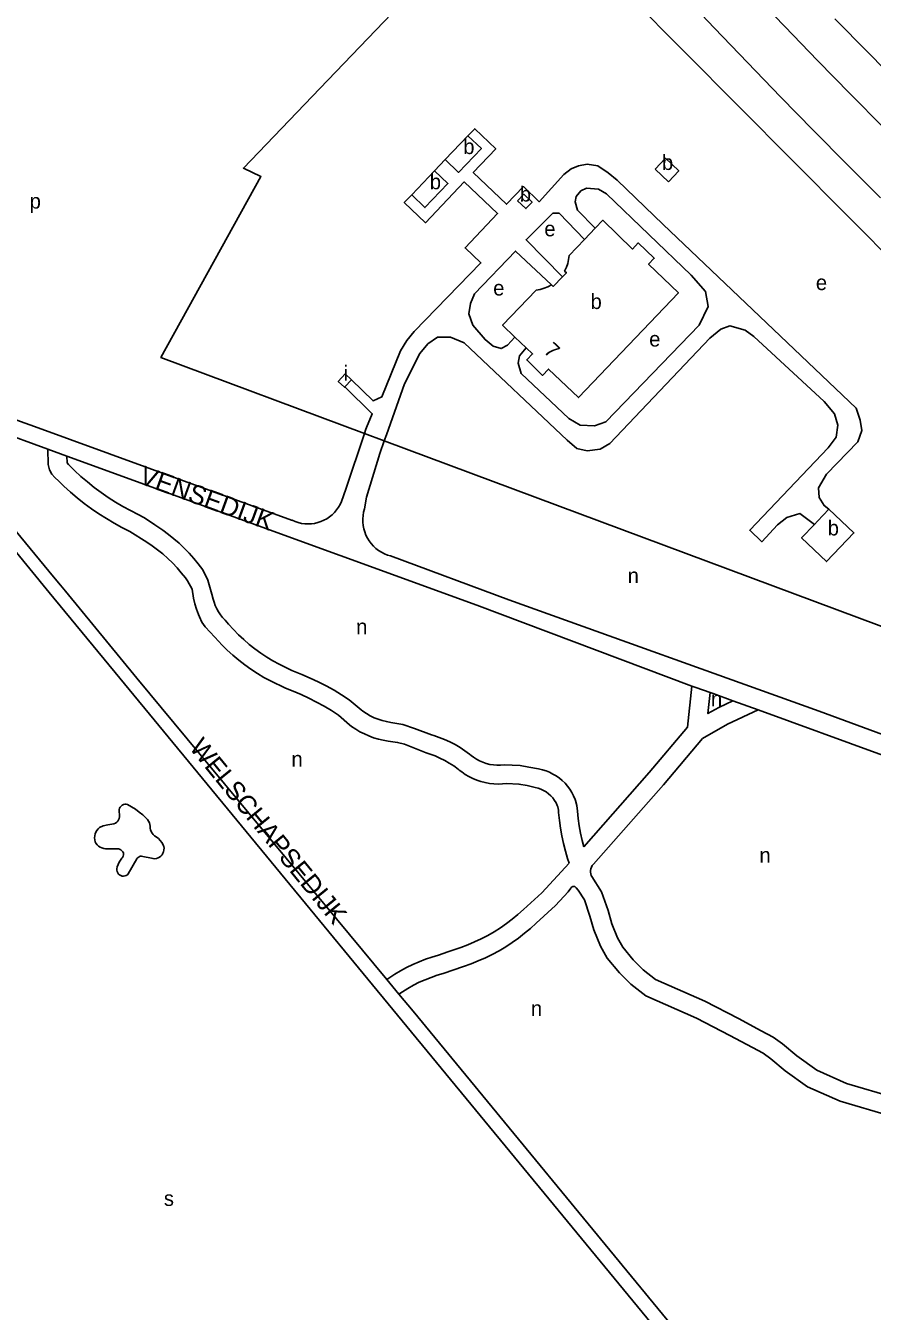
# Model space of a CAD drawing. Extents: x 156066 to 157805, y 383432 to 385631.
# Drawn here: x 156622.4 to 156846.9, y 384832 to 385173.1 of the extents above; entities that cross this region are included whole.
import ezdxf

# ---------------------------------------------------------------- set-up
doc = ezdxf.new("R2010")
doc.units = 0
for name, color, linetype in [('BLT_Basislijn', 7, 'Continuous'), ('BLT_Bebouwing', 7, 'Continuous'), ('BLT_Centroide', 7, 'Continuous'), ('BLT_Huisnummer', 7, 'Continuous'), ('BLT_Straatnaam', 7, 'Continuous')]:
    doc.layers.add(name, color=color, linetype=linetype)

msp = doc.modelspace()

# ---------------------------------------------------------------- linework, layer by layer
at = {"layer": 'BLT_Basislijn'}
for p, q in [((156700.39, 385156.45), (156745.33, 385203.34)), ((156895.07, 385067.48), (156766.62, 385196.86)), ((156733.63, 385137.58), (156730.82, 385134.59)), ((156603.38, 385069.8), (156628.27, 385060.73)), ((156624.71, 385066.73), (156617.54, 385069.34)), ((156692.93, 385041.93), (156624.71, 385066.73)), ((156717.48, 385062.97), (156712.23, 385064.93)), ((156718.04, 385064.52), (156717.48, 385062.97)), ((156871.24, 385005.53), (156717.48, 385062.97)), ((156628.27, 385060.73), (156628.39, 385056.66)), ((156628.27, 385060.73), (156633.33, 385058.89)), ((156633.33, 385058.89), (156633.38, 385057.07)), ((156633.33, 385058.89), (156741.99, 385019.31)), ((156609.93, 385045.44), (156628.64, 385022.72)), ((156619.86, 385038.85), (156629.74, 385026.88)), ((156650.05, 385038.91), (156654.52, 385036.03)), ((156719.12, 385032.41), (156750.56, 385020.74)), ((156629.74, 385026.88), (156631.6, 385024.62)), ((156631.6, 385024.62), (156632.92, 385023.02)), ((156628.64, 385022.72), (156647.34, 385000)), ((156632.92, 385023.02), (156651.9, 385000)), ((156750.56, 385020.74), (156832.8, 384991.18)), ((156799.07, 384997.88), (156741.99, 385019.31)), ((156689.64, 385003.65), (156692.96, 385001.98)), ((156647.34, 385000), (156763.61, 384858.81)), ((156651.9, 385000), (156718.17, 384919.98)), ((156687.33, 384999.22), (156691.26, 384997.28)), ((156799.07, 384997.88), (156797.88, 384986.98)), ((156800.13, 384997.48), (156799.07, 384997.88)), ((156803.91, 384996.14), (156800.13, 384997.48)), ((156708.18, 384994.26), (156711.34, 384991.55)), ((156804.66, 384995.87), (156803.91, 384996.14)), ((156804.66, 384995.87), (156809.95, 384993.95)), ((156809.95, 384993.95), (156816.62, 384991.54)), ((156705.39, 384990.11), (156708.26, 384987.6)), ((156861.75, 384980.58), (156832.8, 384991.18)), ((156740.12, 384979.78), (156740.54, 384979.45)), ((156737.04, 384975.84), (156737.38, 384975.57)), ((156647.21, 384964.76), (156647.24, 384963.57)), ((156643.56, 384954.72), (156646.61, 384954.68)), ((156655.73, 384952.18), (156653.43, 384952.66)), ((156651.88, 384952.06), (156649.62, 384948.06)), ((156766.5, 384950.92), (156759.23, 384943.01)), ((156754.38, 384938.6), (156759.23, 384943.01)), ((156766.28, 384943.3), (156762.91, 384939.62)), ((156766.28, 384943.3), (156766.98, 384944.25)), ((156768.39, 384944.35), (156768.93, 384943.69)), ((156757.81, 384934.96), (156762.91, 384939.62)), ((156733.15, 384921.6), (156738.54, 384923.46)), ((156718.17, 384919.98), (156721.37, 384916.12)), ((156721.37, 384916.12), (156725.11, 384911.6)), ((156725.11, 384911.6), (156823.88, 384791.69)), ((156763.61, 384858.81), (156843.95, 384761.22))]:
    msp.add_line(p, q, dxfattribs=at)
for points in [[(156849.91, 385146.05), (156841.11, 385154.93), (156832.37, 385163.86), (156823.68, 385172.84), (156815.04, 385181.87), (156806.47, 385190.96), (156797.94, 385200.1), (156789.48, 385209.29), (156781.07, 385218.54), (156772.72, 385227.84), (156764.42, 385237.18), (156756.19, 385246.58), (156748.01, 385256.03), (156739.89, 385265.53), (156731.83, 385275.08), (156723.83, 385284.68), (156715.89, 385294.33), (156708, 385304.03), (156700.18, 385313.78), (156692.42, 385323.57), (156684.72, 385333.41), (156677.08, 385343.3), (156669.5, 385353.24), (156661.98, 385363.22)], [(156849.1, 385127.46), (156840.18, 385136.34), (156831.32, 385145.28), (156822.52, 385154.26), (156813.77, 385163.31), (156805.07, 385172.4), (156796.44, 385181.55), (156787.86, 385190.76), (156779.34, 385200.01)], [(156854.62, 385156.98), (156845.78, 385165.94), (156836.99, 385174.95)], [(156712.23, 385064.93), (156658.24, 385085.09), (156684.8, 385133.04), (156680.12, 385135.3), (156700.39, 385156.45)], [(156739.69, 385143.89), (156741.46, 385145.75), (156747.06, 385140.41), (156741.09, 385134.15), (156749.93, 385125.72), (156754.39, 385130.4), (156758.6, 385126.39), (156765.14, 385133.58), (156767.06, 385135.08), (156768.98, 385135.93), (156771.33, 385136.36), (156774.1, 385135.93), (156776.88, 385134.01), (156779.23, 385132.09)], [(156724.76, 385128.23), (156722.79, 385126.17), (156728.39, 385120.83), (156738.71, 385131.65), (156747.55, 385123.22), (156738.9, 385114.15), (156743.12, 385110.14), (156725.42, 385091.92), (156723.5, 385089.57), (156721.79, 385086.8), (156716.88, 385074.62), (156714.54, 385073.55), (156708.79, 385079.13)], [(156755.09, 385087.66), (156753.39, 385085.51), (156752.97, 385083.59), (156753.82, 385080.81), (156766.42, 385068.85), (156769.41, 385067.14), (156773.25, 385066.93), (156776.24, 385067.99), (156801.01, 385093.63), (156803.36, 385098.55), (156802.71, 385102.61), (156798.87, 385106.88), (156776.45, 385128.46), (156774.32, 385129.74), (156771.12, 385129.95), (156769.62, 385129.31), (156768.34, 385127.81), (156768.13, 385126.32), (156768.77, 385124.18), (156773.41, 385119.34)], [(156779.23, 385132.09), (156791.4, 385120.34), (156842.64, 385071.63), (156843.71, 385068.42), (156844.14, 385065.65), (156843.07, 385062.65), (156834.74, 385054.11), (156832.61, 385050.48), (156832.82, 385047.91), (156834.1, 385045.78), (156835.39, 385044.78)], [(156770.58, 385116.38), (156763.86, 385123.33), (156762.15, 385123.33), (156755.1, 385116.28), (156764.71, 385106.45)], [(156761.8, 385104.33), (156752.33, 385113.29), (156741.44, 385101.96), (156740.37, 385099.4), (156739.94, 385096.62), (156741.01, 385093.63), (156744.21, 385089.79), (156746.35, 385088.08), (156748.48, 385087.44), (156750.19, 385088.29), (156752.15, 385090.48)], [(156831.56, 385040.74), (156827.7, 385043.64), (156824.28, 385042.57), (156821.72, 385040.65), (156817.62, 385036.15), (156814.39, 385039.23), (156835.21, 385061.1), (156837.3, 385063.94), (156837.73, 385067.14), (156836.88, 385070.13), (156834.1, 385073.34), (156815.52, 385090.64), (156813.18, 385092.35), (156809.12, 385093.42), (156806.77, 385092.56), (156803.78, 385090.21), (156777.31, 385062.23), (156774.74, 385060.73), (156771.33, 385060.3), (156768.55, 385060.95), (156765.99, 385063.08), (156738.66, 385088.93), (156735.03, 385090.43), (156731.62, 385090.43), (156729.05, 385088.72), (156726.92, 385086.15), (156722.86, 385078.04), (156718.04, 385064.52)], [(156707.05, 385077.3), (156714.32, 385070.13), (156712.78, 385066.46)], [(156706.16, 385046.89), (156707.28, 385050.12), (156712.23, 385064.93)], [(156712.23, 385064.93), (156712.61, 385066.07), (156712.78, 385066.46)], [(156717.48, 385062.97), (156716.29, 385059.61), (156712.82, 385047.98), (156712.22, 385044.89)], [(156628.39, 385056.66), (156628.75, 385055.26), (156629.37, 385054.11), (156630.15, 385053.2), (156631.15, 385052.21)], [(156652.21, 385043.42), (156650.17, 385044.44), (156648.17, 385045.54), (156646.2, 385046.7), (156644.28, 385047.93), (156642.4, 385049.23), (156640.57, 385050.6), (156638.79, 385052.03), (156637.06, 385053.52), (156635.38, 385055.06), (156633.76, 385056.67), (156633.38, 385057.07)], [(156650.05, 385038.91), (156647.93, 385039.97), (156645.85, 385041.11), (156643.8, 385042.31), (156641.8, 385043.58), (156639.85, 385044.92), (156637.94, 385046.32), (156636.08, 385047.78), (156634.27, 385049.31), (156632.51, 385050.9), (156631.15, 385052.21)], [(156706.16, 385046.89), (156705.8, 385046.09), (156705.36, 385045.34), (156704.86, 385044.62), (156704.29, 385043.95), (156703.67, 385043.34), (156702.99, 385042.78), (156702.27, 385042.29), (156701.5, 385041.87), (156700.7, 385041.52), (156699.87, 385041.25), (156699.02, 385041.05), (156698.15, 385040.93), (156697.27, 385040.89), (156696.4, 385040.93), (156695.53, 385041.05), (156694.68, 385041.25), (156693.85, 385041.52), (156693.05, 385041.87), (156692.93, 385041.93)], [(156712.22, 385044.89), (156711.99, 385044.03), (156711.85, 385043.15), (156711.78, 385042.26), (156711.79, 385041.37), (156711.89, 385040.49), (156712.06, 385039.61), (156712.31, 385038.76), (156712.64, 385037.93), (156713.04, 385037.14), (156713.51, 385036.38), (156714.04, 385035.67), (156714.64, 385035.01), (156715.29, 385034.41), (156715.99, 385033.87), (156716.74, 385033.39), (156717.54, 385032.98), (156718.36, 385032.65), (156719.12, 385032.41)], [(156652.21, 385043.42), (156653.72, 385042.57), (156655.2, 385041.65), (156656.63, 385040.67), (156657.19, 385040.26)], [(156657.19, 385040.26), (156658.74, 385039.23), (156660.25, 385038.13), (156661.71, 385036.97), (156663.12, 385035.75), (156664.47, 385034.47), (156665.77, 385033.13), (156667.01, 385031.74), (156668.18, 385030.3), (156669.36, 385028.72)], [(156654.52, 385036.03), (156655.98, 385035.06), (156657.39, 385034.02), (156658.75, 385032.92), (156660.07, 385031.76), (156661.33, 385030.54), (156662.53, 385029.27), (156663.67, 385027.94), (156664.75, 385026.56), (156665.28, 385025.83)], [(156669.36, 385028.72), (156670.74, 385025.97), (156671.77, 385022.28)], [(156665.28, 385025.83), (156666.52, 385023.55), (156666.89, 385021.2)], [(156666.89, 385021.2), (156667.26, 385019.73), (156667.7, 385018.3), (156668.22, 385016.88), (156668.49, 385016.23)], [(156671.77, 385022.28), (156672.11, 385020.96), (156672.35, 385020.16)], [(156672.35, 385020.16), (156672.66, 385019.27), (156673.05, 385018.41), (156673.5, 385017.59), (156674.03, 385016.8), (156674.62, 385016.06), (156675.27, 385015.37)], [(156668.49, 385016.23), (156669.15, 385014.83), (156669.97, 385013.62), (156671.31, 385012.16), (156673.58, 385009.71)], [(156689.64, 385003.65), (156687.96, 385004.58), (156686.32, 385005.57), (156684.72, 385006.63), (156683.17, 385007.75), (156681.66, 385008.94), (156680.21, 385010.19), (156678.81, 385011.5), (156677.47, 385012.87), (156676.18, 385014.3), (156675.27, 385015.37)], [(156687.33, 384999.22), (156685.56, 385000.19), (156683.83, 385001.23), (156682.14, 385002.34), (156680.49, 385003.51), (156678.9, 385004.75), (156677.35, 385006.05), (156675.86, 385007.41), (156674.42, 385008.83), (156673.58, 385009.71)], [(156708.18, 384994.26), (156706.19, 384995.55), (156704.16, 384996.77), (156702.09, 384997.92), (156699.98, 384998.99), (156697.84, 385000), (156695.66, 385000.93), (156693.45, 385001.79), (156692.96, 385001.98)], [(156705.39, 384990.11), (156703.47, 384991.35), (156701.52, 384992.52), (156699.52, 384993.62), (156697.48, 384994.65), (156695.41, 384995.61), (156693.31, 384996.49), (156691.26, 384997.28)], [(156803.91, 384996.14), (156803.3, 384990.56), (156806.17, 384992.2), (156809.95, 384993.95)], [(156719.2, 384988.23), (156718.06, 384988.43), (156716.94, 384988.71), (156715.84, 384989.06), (156714.77, 384989.49), (156713.74, 384990), (156712.74, 384990.57), (156711.78, 384991.22), (156711.34, 384991.55)], [(156801.91, 384984), (156808.47, 384987.75), (156816.62, 384991.54)], [(156816.62, 384991.54), (156849.58, 384979.57), (156878.66, 384968.49), (156944.95, 384943.96), (156988.15, 384927.5)], [(156718.48, 384983.28), (156717.2, 384983.5), (156715.92, 384983.8), (156714.66, 384984.18), (156713.43, 384984.64), (156712.22, 384985.17), (156711.05, 384985.77), (156709.92, 384986.44), (156708.83, 384987.18), (156708.26, 384987.6)], [(156719.2, 384988.23), (156722.42, 384987.65), (156725.53, 384986.64), (156729.99, 384984.94)], [(156797.88, 384986.98), (156787.73, 384974.92), (156770.38, 384955.24)], [(156728.62, 384980.13), (156725.03, 384981.61), (156722.82, 384982.42), (156721.01, 384982.92), (156718.48, 384983.28)], [(156740.12, 384979.78), (156738.88, 384980.69), (156737.6, 384981.55), (156736.27, 384982.33), (156734.9, 384983.05), (156733.5, 384983.69), (156732.07, 384984.26), (156730.61, 384984.75), (156729.99, 384984.94)], [(156801.91, 384984), (156791.52, 384971.65), (156772.94, 384950.59)], [(156737.04, 384975.84), (156735.91, 384976.67), (156734.73, 384977.44), (156733.51, 384978.14), (156732.26, 384978.77), (156730.96, 384979.33), (156729.64, 384979.81), (156728.62, 384980.13)], [(156749.28, 384976.97), (156748.33, 384976.88), (156747.37, 384976.88), (156746.42, 384976.95), (156745.47, 384977.1), (156744.55, 384977.33), (156743.64, 384977.64), (156742.76, 384978.02), (156741.92, 384978.48), (156741.12, 384979), (156740.54, 384979.45)], [(156749.28, 384976.97), (156753.49, 384976.79), (156755.8, 384976.39), (156758.42, 384975.9)], [(156749.94, 384972.01), (156748.8, 384971.9), (156747.65, 384971.87), (156746.51, 384971.92), (156745.37, 384972.05), (156744.24, 384972.25), (156743.13, 384972.54), (156742.04, 384972.9), (156740.98, 384973.34), (156739.95, 384973.85), (156738.96, 384974.43), (156738.02, 384975.08), (156737.38, 384975.57)], [(156758.42, 384975.9), (156759.41, 384975.67), (156760.38, 384975.37), (156761.32, 384974.99), (156762.23, 384974.54), (156763.1, 384974.02), (156763.92, 384973.43), (156764.7, 384972.78), (156765.43, 384972.07), (156766.09, 384971.3), (156766.7, 384970.48), (156767.23, 384969.62), (156767.7, 384968.72), (156768.1, 384967.79), (156768.21, 384967.47)], [(156749.94, 384972.01), (156753.19, 384971.86), (156755.4, 384971.46), (156757.5, 384970.98)], [(156757.5, 384970.98), (156758.27, 384970.8), (156759.02, 384970.54), (156759.74, 384970.2), (156760.42, 384969.79), (156761.06, 384969.32), (156761.64, 384968.79), (156762.17, 384968.2), (156762.64, 384967.55), (156763.04, 384966.87), (156763.37, 384966.15), (156763.49, 384965.83)], [(156649.43, 384966.42), (156649.07, 384966.5), (156648.7, 384966.51), (156648.35, 384966.43), (156648.02, 384966.27), (156647.72, 384966.05), (156647.49, 384965.77), (156647.32, 384965.45), (156647.22, 384965.1), (156647.21, 384964.76)], [(156649.43, 384966.42), (156650.5, 384965.84), (156651.53, 384965.18), (156652.51, 384964.46), (156653.45, 384963.67), (156654.33, 384962.83), (156654.5, 384962.65)], [(156768.21, 384967.47), (156768.51, 384966.15), (156768.7, 384964.67)], [(156647.24, 384963.57), (156647.26, 384963.16), (156647.2, 384962.76), (156647.05, 384962.38), (156646.84, 384962.03), (156646.57, 384961.74), (156646.24, 384961.5), (156645.78, 384961.3)], [(156655.41, 384960.67), (156655.35, 384961.15), (156655.2, 384961.62), (156654.98, 384962.06), (156654.69, 384962.45), (156654.5, 384962.65)], [(156763.49, 384965.83), (156763.69, 384964.94), (156763.71, 384964.29)], [(156763.71, 384964.29), (156763.91, 384962.22), (156764.19, 384960.17), (156764.56, 384958.12), (156765, 384956.09), (156765.51, 384954.08), (156766.11, 384952.09), (156766.5, 384950.92)], [(156768.7, 384964.67), (156768.89, 384962.72), (156769.16, 384960.76), (156769.52, 384958.81), (156769.95, 384956.88), (156770.38, 384955.24)], [(156642.01, 384960.35), (156641.62, 384959.99), (156641.29, 384959.58), (156641.02, 384959.12), (156640.83, 384958.63), (156640.71, 384958.11), (156640.67, 384957.59), (156640.71, 384957.06), (156640.83, 384956.54), (156640.98, 384956.15)], [(156645.78, 384961.3), (156644.19, 384961.07), (156642.96, 384960.83), (156642.01, 384960.35)], [(156655.41, 384960.67), (156655.42, 384960.18), (156655.52, 384959.71), (156655.68, 384959.25), (156655.92, 384958.83), (156656.23, 384958.45), (156656.59, 384958.13), (156657.04, 384957.85)], [(156640.98, 384956.15), (156641.32, 384955.75), (156641.71, 384955.4), (156642.15, 384955.12), (156642.63, 384954.91), (156643.14, 384954.77), (156643.56, 384954.72)], [(156657.04, 384957.85), (156657.58, 384957.4), (156658.06, 384956.89), (156658.49, 384956.33), (156658.84, 384955.72), (156658.94, 384955.51)], [(156646.61, 384954.68), (156646.97, 384954.67), (156647.32, 384954.59), (156647.65, 384954.43), (156647.93, 384954.2), (156648.15, 384953.92), (156648.3, 384953.59), (156648.36, 384953.41)], [(156648.36, 384953.41), (156648.35, 384953.06), (156648.26, 384952.72), (156648.1, 384952.4), (156647.92, 384952.18)], [(156653.43, 384952.66), (156653.11, 384952.72), (156652.79, 384952.7), (156652.48, 384952.6), (156652.2, 384952.43), (156651.97, 384952.2), (156651.88, 384952.06)], [(156655.73, 384952.18), (156656.18, 384952.09), (156656.63, 384952.07), (156657.08, 384952.14), (156657.51, 384952.28), (156657.92, 384952.5), (156658.27, 384952.78), (156658.57, 384953.12), (156658.81, 384953.51), (156658.98, 384953.93), (156659.07, 384954.38), (156659.08, 384954.84), (156659.01, 384955.29), (156658.94, 384955.51)], [(156647.92, 384952.18), (156647.51, 384951.68), (156647.16, 384951.14), (156646.89, 384950.56), (156646.69, 384949.95), (156646.57, 384949.36)], [(156646.57, 384949.36), (156646.57, 384948.99), (156646.65, 384948.63), (156646.8, 384948.29), (156647.02, 384947.99), (156647.3, 384947.75), (156647.63, 384947.57), (156647.98, 384947.46), (156648.35, 384947.43), (156648.72, 384947.49), (156649.07, 384947.62), (156649.38, 384947.82), (156649.62, 384948.06)], [(156772.94, 384950.59), (156772.64, 384950.24), (156772.41, 384949.85), (156772.25, 384949.42), (156772.16, 384948.97), (156772.16, 384948.52), (156772.23, 384948.07), (156772.39, 384947.64), (156772.52, 384947.38)], [(156772.52, 384947.38), (156775.09, 384943.31), (156776.82, 384938.34), (156777.81, 384934.77), (156779.3, 384931.04), (156780.72, 384928.56), (156783.52, 384925.2), (156786.15, 384922.57), (156789.4, 384920.04), (156802.47, 384914.3), (156811.41, 384909.63), (156817.45, 384906.4), (156820.63, 384904.71), (156823.05, 384902.95), (156826.87, 384899.73), (156832.21, 384895.92), (156840.08, 384892.46), (156852.67, 384888.73), (156862.69, 384886.96), (156871.15, 384886.17), (156878.39, 384885.97), (156883.32, 384885.54), (156887.4, 384884.4)], [(156768.39, 384944.35), (156768.22, 384944.54), (156768, 384944.66), (156767.75, 384944.72), (156767.5, 384944.69), (156767.27, 384944.58), (156767.08, 384944.41), (156766.98, 384944.25)], [(156768.93, 384943.69), (156770.55, 384941.13), (156772.04, 384936.85), (156773.06, 384933.17), (156774.79, 384928.86), (156776.59, 384925.7), (156779.83, 384921.82), (156782.83, 384918.82), (156786.82, 384915.71), (156800.31, 384909.79), (156809.08, 384905.2), (156815.1, 384901.99), (156817.97, 384900.46), (156819.97, 384899.01), (156823.8, 384895.78), (156829.72, 384891.55), (156838.35, 384887.76), (156851.52, 384883.85), (156862.02, 384882), (156870.85, 384881.18), (156878.1, 384880.98), (156882.43, 384880.6), (156886.45, 384879.47)], [(156754.38, 384938.6), (156752.93, 384937.29), (156751.43, 384936.05), (156749.87, 384934.87), (156748.27, 384933.75), (156746.63, 384932.7), (156744.94, 384931.72), (156743.21, 384930.81), (156741.45, 384929.97), (156739.66, 384929.2), (156737.83, 384928.51), (156736.96, 384928.2)], [(156757.81, 384934.96), (156756.29, 384933.58), (156754.71, 384932.27), (156753.08, 384931.02), (156751.41, 384929.84), (156749.69, 384928.72), (156747.93, 384927.66), (156746.13, 384926.68), (156744.29, 384925.77), (156742.42, 384924.93), (156740.51, 384924.17), (156738.54, 384923.46)], [(156731.9, 384926.44), (156730.14, 384925.94), (156728.41, 384925.37), (156726.72, 384924.72), (156725.05, 384923.99), (156723.41, 384923.19), (156721.82, 384922.32), (156720.26, 384921.39), (156718.74, 384920.38), (156718.17, 384919.98)], [(156731.9, 384926.44), (156734.38, 384927.32), (156736.96, 384928.2)], [(156733.15, 384921.6), (156731.52, 384921.13), (156729.9, 384920.59), (156728.31, 384919.97), (156726.76, 384919.27), (156725.23, 384918.5), (156723.75, 384917.66), (156722.31, 384916.76), (156721.37, 384916.12)]]:
    msp.add_lwpolyline(points, dxfattribs=at)
at = {"layer": 'BLT_Bebouwing'}
for p, q in [((156733.63, 385137.58), (156739.69, 385143.89)), ((156730.82, 385134.59), (156724.76, 385128.23)), ((156789.34, 385135.04), (156792.82, 385131.7)), ((156770.58, 385116.38), (156773.41, 385119.34)), ((156761.8, 385104.33), (156761.88, 385104.26)), ((156755.09, 385087.66), (156752.15, 385090.48)), ((156708.79, 385079.13), (156707.05, 385077.3))]:
    msp.add_line(p, q, dxfattribs=at)
for points in [[(156739.69, 385143.89), (156743.25, 385140.52), (156737.21, 385134.17), (156733.63, 385137.58)], [(156792.82, 385131.7), (156795.59, 385134.57), (156792.1, 385137.91), (156789.34, 385135.04)], [(156724.76, 385128.23), (156728.27, 385124.82), (156734.35, 385131.18), (156730.82, 385134.59)], [(156773.41, 385119.34), (156775.41, 385121.45), (156783.35, 385113.84), (156784.85, 385115.44), (156789.07, 385111.39), (156787.58, 385109.81), (156795.5, 385102.23), (156768.97, 385074.4), (156761.05, 385081.96), (156759.49, 385080.32), (156755.25, 385084.4), (156756.8, 385086.01), (156755.09, 385087.66)], [(156764.71, 385106.45), (156765.78, 385107.56), (156765.32, 385108), (156765.79, 385108.99), (156766.14, 385110), (156766.36, 385111.03), (156766.51, 385112.11), (156770.58, 385116.38)], [(156761.88, 385104.26), (156762.25, 385103.91), (156764.71, 385106.45)], [(156752.15, 385090.48), (156748.87, 385093.62), (156757.77, 385102.95), (156758.84, 385103.14), (156759.85, 385103.43), (156760.82, 385103.83), (156761.8, 385104.33)], [(156707.05, 385077.3), (156706.9, 385077.15), (156705.29, 385078.73), (156707.15, 385080.71), (156708.79, 385079.13)], [(156835.39, 385044.78), (156842.01, 385038.49), (156834.74, 385030.89), (156828.15, 385037.17), (156831.56, 385040.74)], [(156831.56, 385040.74), (156832.37, 385041.59), (156835.39, 385044.78)]]:
    msp.add_lwpolyline(points, dxfattribs=at)
msp.add_lwpolyline([(156752.86, 385126.62), (156754.51, 385128.36), (156756.68, 385126.29), (156755.03, 385124.55)], close=True, dxfattribs=at)

# ---------------------------------------------------------------- texts
at = {"layer": 'BLT_Centroide'}
for s, p in [('b', (156738.44, 385139.03)), ('b', (156791.13, 385134.81)), ('b', (156729.56, 385129.7)), ('b', (156753.43, 385126.44)), ('p', (156623.46, 385124.56)), ('e', (156759.93, 385117.21)), ('e', (156831.94, 385102.94)), ('e', (156746.38, 385101.51)), ('b', (156772.19, 385097.92)), ('e', (156787.74, 385087.96)), ('i', (156706.69, 385078.94)), ('b', (156835.08, 385037.84)), ('n', (156782.03, 385025.19)), ('n', (156710.02, 385011.64)), ('n', (156804.12, 384992.5)), ('n', (156692.87, 384976.53)), ('n', (156816.97, 384951.01)), ('n', (156756.36, 384910.35)), ('s', (156659.05, 384859.94))]:
    msp.add_text(s, height=4, dxfattribs=at).set_placement(p)
at = {"layer": 'BLT_Huisnummer'}
msp.add_text('7', height=4, rotation=316.3584, dxfattribs=at).set_placement((156759.52, 385086.55))
at = {"layer": 'BLT_Straatnaam'}
for s, rotation, p in [('VENSEDIJK', 339.9852, (156652.17, 385051.74)), ('WELSCHAPSEDIJK', 309.1929, (156665.58, 384981.47))]:
    msp.add_text(s, height=5, rotation=rotation, dxfattribs=at).set_placement(p)

doc.saveas('drawing.dxf')
